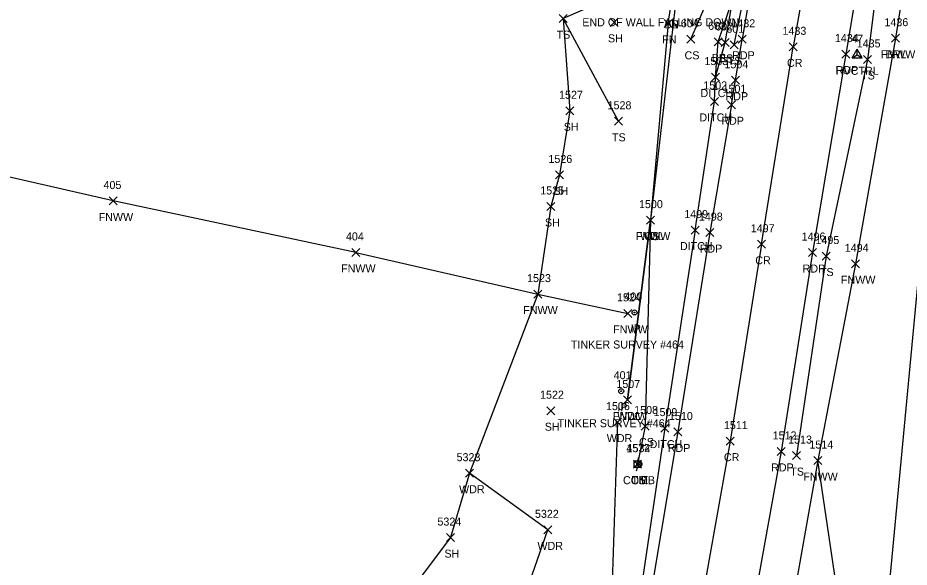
# Model space of a CAD drawing. Extents: x 1509053 to 1511576, y 400838 to 402572.
# Drawn here: x 1509568.8 to 1509791.5, y 401286.1 to 401423.4 of the extents above; entities that cross this region are included whole.
import ezdxf

# ---------------------------------------------------------------- set-up
doc = ezdxf.new("R2010")
doc.units = 0
for name, color, linetype in [('C_A', 7, 'Continuous'), ('C_I', 7, 'Continuous'), ('CBP', 7, 'Continuous'), ('CPSM', 7, 'Continuous'), ('D_A', 7, 'Continuous'), ('D_I', 7, 'Continuous'), ('D_TIC', 7, 'Continuous'), ('DD', 7, 'Continuous'), ('L_A', 7, 'Continuous'), ('L_C', 7, 'Continuous'), ('L_I', 7, 'Continuous'), ('L_TIC', 7, 'Continuous'), ('LABL', 7, 'Continuous'), ('LAWA', 7, 'Continuous'), ('LELB', 7, 'Continuous'), ('LFNC', 7, 'Continuous'), ('LSOGP', 7, 'Continuous'), ('M_A', 7, 'Continuous'), ('M_C', 7, 'Continuous'), ('M_I', 7, 'Continuous'), ('MPIR', 7, 'Continuous'), ('P_A', 7, 'Continuous'), ('P_I', 7, 'Continuous'), ('P_TIC', 7, 'Continuous'), ('PET', 7, 'Continuous'), ('PRC', 7, 'Continuous'), ('U_A', 7, 'Continuous'), ('U_I', 7, 'Continuous'), ('UP', 7, 'Continuous')]:
    doc.layers.add(name, color=color, linetype=linetype)

msp = doc.modelspace()

# ---------------------------------------------------------------- linework, layer by layer
at = {"layer": 'CBP'}
for radius in [0.625, 0.0833]:
    msp.add_circle((1509724.11, 401311.86), radius, dxfattribs=at)
at = {"layer": 'CPSM'}
for p, q in [((1509777.26, 401413.39), (1509778.51, 401415.56)), ((1509779.76, 401413.39), (1509778.51, 401415.56)), ((1509778.51, 401414.12), (1509778.51, 401415.56)), ((1509777.26, 401413.39), (1509778.51, 401414.12)), ((1509777.26, 401413.39), (1509779.76, 401413.39)), ((1509778.51, 401414.12), (1509778.51, 401414.12)), ((1509778.51, 401414.12), (1509779.76, 401413.39))]:
    msp.add_line(p, q, dxfattribs=at)
at = {"layer": 'D_TIC'}
for points in [[(1509742.13, 401407.55), (1509744.13, 401409.55)], [(1509744.13, 401407.55), (1509742.13, 401409.55)], [(1509741.86, 401401.48), (1509743.86, 401403.48)], [(1509743.86, 401401.48), (1509741.86, 401403.48)], [(1509737.02, 401369.33), (1509739.02, 401371.33)], [(1509739.02, 401369.33), (1509737.02, 401371.33)], [(1509729.43, 401319.85), (1509731.43, 401321.85)], [(1509731.43, 401319.85), (1509729.43, 401321.85)]]:
    msp.add_lwpolyline(points, dxfattribs=at)
at = {"layer": 'DD'}
for points in [[(1509743.13, 401408.55), (1509743.77, 401417.36)], [(1509743.13, 401408.55), (1509745.54, 401417.2)], [(1509738.02, 401370.33), (1509742.86, 401402.48), (1509743.13, 401408.55)], [(1509738.02, 401370.33), (1509730.43, 401320.85)], [(1509730.43, 401320.85), (1509723.02, 401270.7)]]:
    msp.add_lwpolyline(points, dxfattribs=at)
at = {"layer": 'L_TIC'}
for points in [[(1509704.02, 401422.16), (1509706.02, 401424.16)], [(1509706.02, 401422.16), (1509704.02, 401424.16)], [(1509716.77, 401421.23), (1509718.77, 401423.23)], [(1509718.77, 401421.23), (1509716.77, 401423.23)], [(1509730.33, 401420.95), (1509732.33, 401422.95)], [(1509732.33, 401420.95), (1509730.33, 401422.95)], [(1509787.09, 401417.27), (1509789.09, 401419.27)], [(1509789.09, 401417.27), (1509787.09, 401419.27)], [(1509787.09, 401417.27), (1509789.09, 401419.27)], [(1509789.09, 401417.27), (1509787.09, 401419.27)], [(1509735.96, 401416.99), (1509737.96, 401418.99)], [(1509737.96, 401416.99), (1509735.96, 401418.99)], [(1509742.77, 401416.36), (1509744.77, 401418.36)], [(1509744.77, 401416.36), (1509742.77, 401418.36)], [(1509744.54, 401416.2), (1509746.54, 401418.2)], [(1509746.54, 401416.2), (1509744.54, 401418.2)], [(1509746.77, 401415.63), (1509748.77, 401417.63)], [(1509748.77, 401415.63), (1509746.77, 401417.63)], [(1509780.12, 401411.96), (1509782.12, 401413.96)], [(1509782.12, 401411.96), (1509780.12, 401413.96)], [(1509705.73, 401399.13), (1509707.73, 401401.13)], [(1509707.73, 401399.13), (1509705.73, 401401.13)], [(1509717.86, 401396.51), (1509719.86, 401398.51)], [(1509719.86, 401396.51), (1509717.86, 401398.51)], [(1509703.13, 401383.1), (1509705.13, 401385.1)], [(1509705.13, 401383.1), (1509703.13, 401385.1)], [(1509591.63, 401376.6), (1509593.63, 401378.6)], [(1509593.63, 401376.6), (1509591.63, 401378.6)], [(1509701.02, 401375.22), (1509703.02, 401377.22)], [(1509703.02, 401375.22), (1509701.02, 401377.22)], [(1509725.88, 401371.81), (1509727.88, 401373.81)], [(1509727.88, 401371.81), (1509725.88, 401373.81)], [(1509725.88, 401371.81), (1509727.88, 401373.81)], [(1509727.88, 401371.81), (1509725.88, 401373.81)], [(1509725.88, 401371.81), (1509727.88, 401373.81)], [(1509727.88, 401371.81), (1509725.88, 401373.81)], [(1509652.22, 401363.75), (1509654.22, 401365.75)], [(1509654.22, 401363.75), (1509652.22, 401365.75)], [(1509769.82, 401362.84), (1509771.82, 401364.84)], [(1509771.82, 401362.84), (1509769.82, 401364.84)], [(1509777.14, 401360.9), (1509779.14, 401362.9)], [(1509779.14, 401360.9), (1509777.14, 401362.9)], [(1509697.74, 401353.33), (1509699.74, 401355.33)], [(1509699.74, 401353.33), (1509697.74, 401355.33)], [(1509720.21, 401348.52), (1509722.21, 401350.52)], [(1509722.21, 401348.52), (1509720.21, 401350.52)], [(1509720.13, 401326.88), (1509722.13, 401328.88)], [(1509722.13, 401326.88), (1509720.13, 401328.88)], [(1509720.13, 401326.88), (1509722.13, 401328.88)], [(1509722.13, 401326.88), (1509720.13, 401328.88)], [(1509700.99, 401324.2), (1509702.99, 401326.2)], [(1509702.99, 401324.2), (1509700.99, 401326.2)], [(1509717.6, 401321.35), (1509719.6, 401323.35)], [(1509719.6, 401321.35), (1509717.6, 401323.35)], [(1509724.58, 401320.38), (1509726.58, 401322.38)], [(1509726.58, 401320.38), (1509724.58, 401322.38)], [(1509762.41, 401312.99), (1509764.41, 401314.99)], [(1509764.41, 401312.99), (1509762.41, 401314.99)], [(1509722.61, 401310.84), (1509724.61, 401312.84)], [(1509724.61, 401310.84), (1509722.61, 401312.84)], [(1509767.73, 401311.75), (1509769.72, 401313.75)], [(1509769.72, 401311.75), (1509767.73, 401313.75)], [(1509680.69, 401308.59), (1509682.69, 401310.59)], [(1509682.69, 401308.59), (1509680.69, 401310.59)], [(1509700.27, 401294.44), (1509702.27, 401296.44)], [(1509702.27, 401294.44), (1509700.27, 401296.44)], [(1509675.9, 401292.5), (1509677.9, 401294.5)], [(1509677.9, 401292.5), (1509675.9, 401294.5)]]:
    msp.add_lwpolyline(points, dxfattribs=at)
at = {"layer": 'LABL'}
msp.add_lwpolyline([(1509804.43, 401450.94), (1509793.73, 401453.86), (1509788.09, 401418.27)], dxfattribs=at)
at = {"layer": 'LAWA'}
for points in [[(1509733.42, 401429.22), (1509726.88, 401372.81)], [(1509721.13, 401327.88), (1509726.88, 401372.81)], [(1509718.6, 401322.35), (1509716.94, 401272.36)], [(1509637.97, 401175.99), (1509638.56, 401199.24), (1509647.06, 401226.82), (1509648.79, 401232.51), (1509655.32, 401230.31), (1509660.07, 401236.87), (1509656.2, 401240.16), (1509659.66, 401243.72), (1509666.3, 401249.98), (1509674.22, 401256.95), (1509687.01, 401273.48), (1509695.42, 401278.73), (1509701.27, 401295.44), (1509681.69, 401309.59)]]:
    msp.add_lwpolyline(points, dxfattribs=at)
at = {"layer": 'LELB'}
for points in [[(1509747.77, 401416.63), (1509750.21, 401428.63), (1509752.14, 401443.01), (1509750.46, 401466.15), (1509760.48, 401503.51), (1509765.49, 401528.65), (1509770.9, 401551.56), (1509776.3, 401572.59), (1509780.48, 401596.32), (1509778.93, 401605.73), (1509782.51, 401627.45), (1509784.95, 401662.22), (1509781.8, 401680.58), (1509772.99, 401719.38), (1509769.17, 401721), (1509769.65, 401723.75), (1509771.91, 401724.32), (1509762.66, 401754.93), (1509756.13, 401775.54), (1509751.07, 401789.41), (1509736.27, 401824.32), (1509727.62, 401840.87), (1509712.26, 401861.01), (1509694.01, 401878.11)], [(1509745.54, 401417.2), (1509747.58, 401428.44), (1509752.14, 401443.01), (1509755.83, 401464.96), (1509763.87, 401503), (1509769.15, 401528.1), (1509775.42, 401550.94), (1509779.3, 401571.9), (1509785.18, 401596.41), (1509784.53, 401607.91), (1509782.51, 401627.45), (1509780.91, 401662.72), (1509779.34, 401679.41)], [(1509804.85, 401507.7), (1509787.26, 401462.24), (1509781.12, 401412.96), (1509770.82, 401363.84), (1509763.41, 401313.99)], [(1509736.96, 401417.99), (1509743.72, 401433.71)], [(1509743.77, 401417.36), (1509747.58, 401428.44)], [(1509718.86, 401397.51), (1509705.02, 401423.16)], [(1509726.88, 401372.81), (1509725.58, 401321.38), (1509723.61, 401311.84)], [(1509784.91, 401263.98), (1509794.11, 401361.03)], [(1509776.02, 401263.24), (1509768.73, 401312.75)]]:
    msp.add_lwpolyline(points, dxfattribs=at)
at = {"layer": 'LFNC'}
for points in [[(1509653.22, 401364.75), (1509592.63, 401377.6), (1509551.33, 401387.07), (1509517.68, 401394.8), (1509507.55, 401397.3), (1509482, 401403.15), (1509405.33, 401420.58), (1509342.12, 401434.67), (1509296.16, 401445.22), (1509229.42, 401460.13)], [(1509731.33, 401421.95), (1509731.91, 401425.72)], [(1509731.33, 401421.95), (1509726.88, 401372.81)], [(1509788.09, 401418.27), (1509778.14, 401361.9), (1509768.73, 401312.75), (1509760.17, 401264.81)], [(1509726.88, 401372.81), (1509721.13, 401327.88)], [(1509653.22, 401364.75), (1509698.74, 401354.33)], [(1509698.74, 401354.33), (1509721.21, 401349.52)]]:
    msp.add_lwpolyline(points, dxfattribs=at)
at = {"layer": 'LSOGP'}
msp.add_lwpolyline([(1509718.39, 401429.02), (1509705.02, 401423.16), (1509706.73, 401400.13), (1509704.13, 401384.1), (1509702.02, 401376.22), (1509698.74, 401354.33), (1509681.69, 401309.59), (1509676.9, 401293.5), (1509664, 401276.38)], dxfattribs=at)
at = {"layer": 'MPIR'}
for centre, radius in [((1509722.89, 401349.74), 0.625), ((1509722.89, 401349.74), 0.0833), ((1509719.56, 401330.07), 0.625), ((1509719.56, 401330.07), 0.0833)]:
    msp.add_circle(centre, radius, dxfattribs=at)
at = {"layer": 'P_TIC'}
for points in [[(1509748.79, 401417), (1509750.79, 401419)], [(1509750.79, 401417), (1509748.79, 401419)], [(1509761.57, 401415.11), (1509763.57, 401417.11)], [(1509763.57, 401415.11), (1509761.57, 401417.11)], [(1509774.66, 401413.3), (1509776.66, 401415.3)], [(1509776.66, 401413.3), (1509774.66, 401415.3)], [(1509747.14, 401406.75), (1509749.14, 401408.75)], [(1509749.14, 401406.75), (1509747.14, 401408.75)], [(1509746.09, 401400.63), (1509748.09, 401402.63)], [(1509748.09, 401400.63), (1509746.09, 401402.63)], [(1509740.68, 401368.7), (1509742.68, 401370.7)], [(1509742.68, 401368.7), (1509740.68, 401370.7)], [(1509753.64, 401365.79), (1509755.64, 401367.79)], [(1509755.64, 401365.79), (1509753.64, 401367.79)], [(1509766.41, 401363.72), (1509768.41, 401365.72)], [(1509768.41, 401363.72), (1509766.41, 401365.72)], [(1509732.72, 401318.89), (1509734.72, 401320.89)], [(1509734.72, 401318.89), (1509732.72, 401320.89)], [(1509745.79, 401316.6), (1509747.79, 401318.6)], [(1509747.79, 401316.6), (1509745.79, 401318.6)], [(1509758.54, 401314.04), (1509760.54, 401316.04)], [(1509760.54, 401314.04), (1509758.54, 401316.04)]]:
    msp.add_lwpolyline(points, dxfattribs=at)
at = {"layer": 'PET'}
for points in [[(1509690.27, 401895.46), (1509701.64, 401882.87), (1509726.68, 401848.01), (1509747.74, 401803.41), (1509763.81, 401758.01), (1509775.46, 401713.07), (1509786.05, 401661.7), (1509787.8, 401644.85), (1509788.16, 401621.99), (1509786.62, 401596.26), (1509780.1, 401566.45), (1509768.35, 401517.81), (1509758.18, 401467.69), (1509749.79, 401418)], [(1509812.34, 401557.62), (1509800.22, 401536.88), (1509792.46, 401505.8), (1509783.79, 401462.54), (1509775.66, 401414.3), (1509767.41, 401364.72), (1509759.54, 401315.03), (1509750.83, 401266.46)], [(1509748.14, 401407.75), (1509749.79, 401418)], [(1509747.09, 401401.63), (1509748.14, 401407.75)], [(1509747.09, 401401.63), (1509741.68, 401369.7)], [(1509741.68, 401369.7), (1509733.72, 401319.89), (1509725.35, 401270.12)]]:
    msp.add_lwpolyline(points, dxfattribs=at)
at = {"layer": 'PRC'}
for points in [[(1509781.27, 401514.31), (1509771.28, 401465.39), (1509762.57, 401416.11)], [(1509754.64, 401366.79), (1509762.57, 401416.11)], [(1509754.64, 401366.79), (1509746.79, 401317.6), (1509738.04, 401268.43)]]:
    msp.add_lwpolyline(points, dxfattribs=at)
at = {"layer": 'UP'}
for p, q in [((1509722.78, 401311), (1509722.78, 401312.67)), ((1509722.78, 401312.67), (1509724.45, 401312.67)), ((1509723.86, 401313.5), (1509723.61, 401312.67)), ((1509724.45, 401312.67), (1509724.45, 401311)), ((1509724.45, 401311), (1509722.78, 401311)), ((1509723.36, 401310.17), (1509723.61, 401311)), ((1509723.61, 401311.84), (1509723.61, 401311.84))]:
    msp.add_line(p, q, dxfattribs=at)
msp.add_circle((1509723.61, 401311.84), 0.833, dxfattribs=at)

# ---------------------------------------------------------------- texts
at = {"layer": 'C_A'}
for s, p in [('HVCTRL', (1509773.2, 401409.12)), ('TIE', (1509722.19, 401306.86))]:
    msp.add_text(s, height=2, dxfattribs=at).set_placement(p)
at = {"layer": 'C_I'}
for s, p in [('47', (1509777.04, 401417.12)), ('4572', (1509720.85, 401314.86))]:
    msp.add_text(s, height=2, dxfattribs=at).set_placement(p)
at = {"layer": 'D_A'}
for p in [(1509739.37, 401403.55), (1509739.1, 401397.48), (1509734.25, 401365.33), (1509726.67, 401315.85)]:
    msp.add_text('DITCH', height=2, dxfattribs=at).set_placement(p)
at = {"layer": 'D_I'}
for s, p in [('1503', (1509740.36, 401411.55)), ('1502', (1509740.09, 401405.48)), ('1499', (1509735.32, 401373.33)), ('1509', (1509727.65, 401323.85))]:
    msp.add_text(s, height=2, dxfattribs=at).set_placement(p)
at = {"layer": 'L_A'}
for s, p in [('BS', (1509730.35, 401420.72)), ('FN', (1509730.39, 401420.72)), ('TS', (1509703.43, 401418.16)), ('SH', (1509716.26, 401417.23)), ('FN', (1509729.81, 401416.95)), ('CS', (1509735.4, 401412.99)), ('FNWW', (1509784.44, 401413.27)), ('BRL', (1509785.64, 401413.27)), ('BS', (1509742.21, 401412.36)), ('BS', (1509743.98, 401412.2)), ('TS', (1509746.18, 401411.63)), ('TS', (1509779.53, 401407.96)), ('SH', (1509705.22, 401395.13)), ('TS', (1509717.27, 401392.51)), ('SH', (1509702.62, 401379.1)), ('FNWW', (1509588.98, 401372.6)), ('SH', (1509700.51, 401371.22)), ('FNWW', (1509723.22, 401367.81)), ('WDL', (1509724.29, 401367.81)), ('CS', (1509725.32, 401367.81)), ('FNWW', (1509649.57, 401359.75)), ('TS', (1509769.23, 401358.84)), ('FNWW', (1509774.48, 401356.9)), ('FNWW', (1509695.09, 401349.33)), ('FNWW', (1509717.56, 401344.52)), ('FNWW', (1509717.48, 401322.88)), ('WDL', (1509718.55, 401322.88)), ('SH', (1509700.47, 401320.2)), ('WDR', (1509715.96, 401317.35)), ('CS', (1509724.03, 401316.38)), ('TS', (1509761.82, 401308.99)), ('CS', (1509722.05, 401306.84)), ('FNWW', (1509765.07, 401307.75)), ('WDR', (1509679.05, 401304.59)), ('WDR', (1509698.63, 401290.44)), ('SH', (1509675.39, 401288.5))]:
    msp.add_text(s, height=2, dxfattribs=at).set_placement(p)
at = {"layer": 'L_C'}
msp.add_text('END OF WALL FALLING DOWN', height=2, dxfattribs=at).set_placement((1509709.84, 401421.25))
at = {"layer": 'L_I'}
for s, p in [('604', (1509734.47, 401420.99)), ('603', (1509741.29, 401420.36)), ('602', (1509743.05, 401420.2)), ('601', (1509745.85, 401419.63)), ('1436', (1509785.35, 401421.27)), ('1436', (1509785.35, 401421.27)), ('1435', (1509778.43, 401415.96)), ('1527', (1509704.04, 401403.13)), ('1528', (1509716.17, 401400.51)), ('1526', (1509701.38, 401387.1)), ('405', (1509590.19, 401380.6)), ('1525', (1509699.33, 401379.22)), ('1500', (1509724.02, 401375.81)), ('1500', (1509724.02, 401375.81)), ('1500', (1509724.02, 401375.81)), ('404', (1509650.78, 401367.75)), ('1495', (1509768.12, 401366.84)), ('1494', (1509775.44, 401364.9)), ('1523', (1509696.05, 401357.33)), ('1524', (1509718.52, 401352.52)), ('1507', (1509718.36, 401330.88)), ('1507', (1509718.36, 401330.88)), ('1522', (1509699.29, 401328.2)), ('1506', (1509715.78, 401325.35)), ('1508', (1509722.81, 401324.38)), ('1513', (1509761.28, 401316.99)), ('1534', (1509720.92, 401314.84)), ('1514', (1509766.6, 401315.75)), ('5323', (1509678.43, 401312.59)), ('5322', (1509698.01, 401298.44)), ('5324', (1509673.64, 401296.5))]:
    msp.add_text(s, height=2, dxfattribs=at).set_placement(p)
at = {"layer": 'M_A'}
for p in [(1509721.94, 401344.74), (1509718.61, 401325.07)]:
    msp.add_text('IP', height=2, dxfattribs=at).set_placement(p)
at = {"layer": 'M_C'}
for p in [(1509707, 401340.74), (1509703.67, 401321.07)]:
    msp.add_text('TINKER SURVEY #464', height=2, dxfattribs=at).set_placement(p)
at = {"layer": 'M_I'}
for s, p in [('400', (1509720.36, 401352.74)), ('401', (1509717.68, 401333.07))]:
    msp.add_text(s, height=2, dxfattribs=at).set_placement(p)
at = {"layer": 'P_A'}
for s, p in [('RDP', (1509747.28, 401413)), ('CR', (1509761, 401411.11)), ('RDP', (1509773.14, 401409.3)), ('RDP', (1509745.63, 401402.75)), ('RDP', (1509744.58, 401396.63)), ('RDP', (1509739.17, 401364.7)), ('CR', (1509753.07, 401361.79)), ('RDP', (1509764.9, 401359.72)), ('RDP', (1509731.21, 401314.89)), ('CR', (1509745.23, 401312.6)), ('RDP', (1509757.03, 401310.03))]:
    msp.add_text(s, height=2, dxfattribs=at).set_placement(p)
at = {"layer": 'P_I'}
for s, p in [('1432', (1509747.1, 401421)), ('1433', (1509759.87, 401419.11)), ('1434', (1509772.96, 401417.3)), ('1504', (1509745.37, 401410.75)), ('1501', (1509744.89, 401404.63)), ('1498', (1509738.99, 401372.7)), ('1497', (1509751.95, 401369.79)), ('1496', (1509764.66, 401367.72)), ('1510', (1509731.51, 401322.89)), ('1511', (1509745.24, 401320.6)), ('1512', (1509757.42, 401318.03))]:
    msp.add_text(s, height=2, dxfattribs=at).set_placement(p)
at = {"layer": 'U_A'}
msp.add_text('COMB', height=2, dxfattribs=at).set_placement((1509720, 401306.84))
at = {"layer": 'U_I'}
msp.add_text('1534', height=2, dxfattribs=at).set_placement((1509720.92, 401314.84))

doc.saveas('drawing.dxf')
